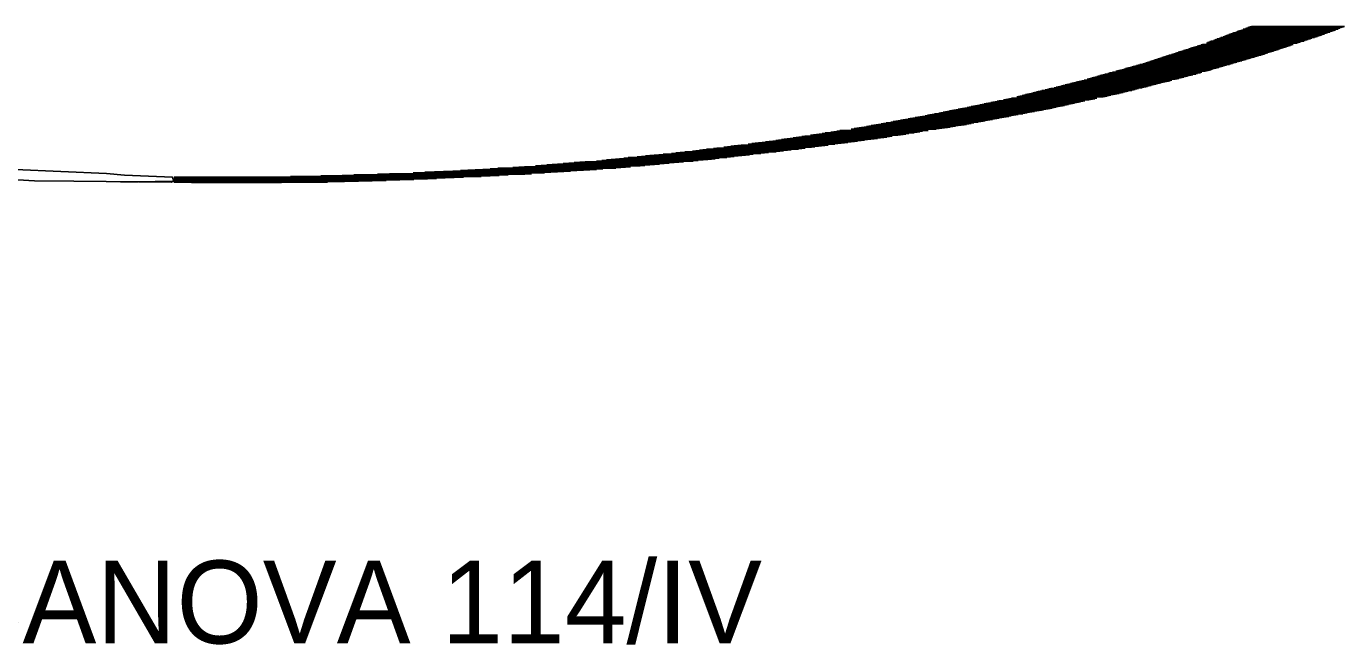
# Model space of a CAD drawing. Extents: x -706631 to -706106, y -1036183 to -1035074.
# Drawn here: x -706129.35 to -706117.43, y -1035971.15 to -1035965.56 of the extents above; entities that cross this region are included whole.
import ezdxf

# ---------------------------------------------------------------- set-up
doc = ezdxf.new("R2010")
doc.units = 0
doc.layers.add('Vrstva 54', color=7, linetype='Continuous')

msp = doc.modelspace()

# ---------------------------------------------------------------- linework, layer by layer
at = {"layer": 'Vrstva 54'}
for p, q in [((-706118.296, -1035965.565), (-706117.453, -1035965.565)), ((-706118.286, -1035965.561), (-706117.442, -1035965.561)), ((-706118.274, -1035965.558), (-706117.431, -1035965.558)), ((-706118.617, -1035965.685), (-706117.787, -1035965.685)), ((-706118.606, -1035965.681), (-706117.774, -1035965.681)), ((-706118.595, -1035965.678), (-706117.762, -1035965.678)), ((-706118.584, -1035965.672), (-706117.749, -1035965.672)), ((-706118.574, -1035965.67), (-706117.738, -1035965.67)), ((-706118.563, -1035965.665), (-706117.726, -1035965.665)), ((-706118.552, -1035965.66), (-706117.713, -1035965.66)), ((-706118.541, -1035965.658), (-706117.702, -1035965.658)), ((-706118.53, -1035965.653), (-706117.689, -1035965.653)), ((-706118.52, -1035965.649), (-706117.677, -1035965.649)), ((-706118.509, -1035965.645), (-706117.665, -1035965.645)), ((-706118.499, -1035965.642), (-706117.653, -1035965.642)), ((-706118.489, -1035965.638), (-706117.641, -1035965.638)), ((-706118.477, -1035965.633), (-706117.63, -1035965.633)), ((-706118.468, -1035965.63), (-706117.62, -1035965.63)), ((-706118.457, -1035965.626), (-706117.609, -1035965.626)), ((-706118.445, -1035965.621), (-706117.597, -1035965.621)), ((-706118.435, -1035965.617), (-706117.587, -1035965.617)), ((-706118.414, -1035965.61), (-706117.566, -1035965.61)), ((-706118.403, -1035965.605), (-706117.558, -1035965.605)), ((-706118.393, -1035965.603), (-706117.547, -1035965.603)), ((-706118.381, -1035965.598), (-706117.536, -1035965.598)), ((-706118.371, -1035965.594), (-706117.526, -1035965.594)), ((-706118.361, -1035965.591), (-706117.514, -1035965.591)), ((-706118.349, -1035965.584), (-706117.504, -1035965.584)), ((-706118.339, -1035965.582), (-706117.493, -1035965.582)), ((-706118.328, -1035965.577), (-706117.483, -1035965.577)), ((-706118.318, -1035965.574), (-706117.474, -1035965.574)), ((-706118.307, -1035965.569), (-706117.463, -1035965.569)), ((-706118.962, -1035965.8), (-706118.137, -1035965.8)), ((-706118.947, -1035965.798), (-706118.125, -1035965.798)), ((-706118.935, -1035965.793), (-706118.112, -1035965.793)), ((-706118.924, -1035965.788), (-706118.1, -1035965.788)), ((-706118.911, -1035965.786), (-706118.088, -1035965.786)), ((-706118.9, -1035965.782), (-706118.075, -1035965.782)), ((-706118.887, -1035965.776), (-706118.064, -1035965.776)), ((-706118.876, -1035965.774), (-706118.052, -1035965.774)), ((-706118.863, -1035965.769), (-706118.04, -1035965.769)), ((-706118.85, -1035965.767), (-706118.029, -1035965.767)), ((-706118.839, -1035965.761), (-706118.015, -1035965.761)), ((-706118.826, -1035965.756), (-706118.003, -1035965.756)), ((-706118.814, -1035965.753), (-706117.991, -1035965.753)), ((-706118.802, -1035965.749), (-706117.98, -1035965.749)), ((-706118.789, -1035965.745), (-706117.968, -1035965.745)), ((-706118.776, -1035965.742), (-706117.956, -1035965.742)), ((-706118.764, -1035965.737), (-706117.944, -1035965.737)), ((-706118.752, -1035965.735), (-706117.931, -1035965.735)), ((-706118.74, -1035965.73), (-706117.919, -1035965.73)), ((-706118.728, -1035965.725), (-706117.908, -1035965.725)), ((-706118.716, -1035965.722), (-706117.895, -1035965.722)), ((-706118.681, -1035965.71), (-706117.859, -1035965.71)), ((-706118.67, -1035965.705), (-706117.847, -1035965.705)), ((-706118.659, -1035965.702), (-706117.834, -1035965.702)), ((-706118.649, -1035965.696), (-706117.823, -1035965.696)), ((-706118.639, -1035965.693), (-706117.81, -1035965.693)), ((-706118.628, -1035965.691), (-706117.799, -1035965.691)), ((-706119.342, -1035965.92), (-706118.543, -1035965.92)), ((-706119.327, -1035965.917), (-706118.528, -1035965.917)), ((-706119.313, -1035965.913), (-706118.514, -1035965.913)), ((-706119.299, -1035965.91), (-706118.5, -1035965.91)), ((-706119.284, -1035965.904), (-706118.487, -1035965.904)), ((-706119.27, -1035965.902), (-706118.473, -1035965.902)), ((-706119.256, -1035965.896), (-706118.46, -1035965.896)), ((-706119.242, -1035965.895), (-706118.445, -1035965.895)), ((-706119.23, -1035965.889), (-706118.432, -1035965.889)), ((-706119.218, -1035965.885), (-706118.418, -1035965.885)), ((-706119.206, -1035965.881), (-706118.405, -1035965.881)), ((-706119.194, -1035965.876), (-706118.391, -1035965.876)), ((-706119.182, -1035965.873), (-706118.378, -1035965.873)), ((-706119.169, -1035965.869), (-706118.362, -1035965.869)), ((-706119.157, -1035965.865), (-706118.348, -1035965.865)), ((-706119.144, -1035965.861), (-706118.335, -1035965.861)), ((-706119.132, -1035965.858), (-706118.321, -1035965.858)), ((-706119.121, -1035965.853), (-706118.308, -1035965.853)), ((-706119.106, -1035965.849), (-706118.294, -1035965.849)), ((-706119.095, -1035965.846), (-706118.281, -1035965.846)), ((-706119.083, -1035965.841), (-706118.266, -1035965.841)), ((-706119.071, -1035965.837), (-706118.253, -1035965.837)), ((-706119.059, -1035965.834), (-706118.24, -1035965.834)), ((-706119.047, -1035965.828), (-706118.226, -1035965.828)), ((-706119.034, -1035965.826), (-706118.211, -1035965.826)), ((-706119.021, -1035965.82), (-706118.198, -1035965.82)), ((-706119.01, -1035965.819), (-706118.185, -1035965.819)), ((-706118.998, -1035965.813), (-706118.172, -1035965.813)), ((-706118.985, -1035965.809), (-706118.16, -1035965.809)), ((-706118.973, -1035965.806), (-706118.149, -1035965.806)), ((-706119.759, -1035966.037), (-706118.963, -1035966.037)), ((-706119.745, -1035966.032), (-706118.946, -1035966.032)), ((-706119.731, -1035966.029), (-706118.931, -1035966.029)), ((-706119.717, -1035966.025), (-706118.916, -1035966.025)), ((-706119.702, -1035966.022), (-706118.9, -1035966.022)), ((-706119.688, -1035966.017), (-706118.885, -1035966.017)), ((-706119.673, -1035966.013), (-706118.869, -1035966.013)), ((-706119.659, -1035966.01), (-706118.852, -1035966.01)), ((-706119.644, -1035966.004), (-706118.837, -1035966.004)), ((-706119.63, -1035966), (-706118.82, -1035966)), ((-706119.615, -1035965.997), (-706118.805, -1035965.997)), ((-706119.601, -1035965.992), (-706118.79, -1035965.992)), ((-706119.586, -1035965.99), (-706118.776, -1035965.99)), ((-706119.573, -1035965.985), (-706118.763, -1035965.985)), ((-706119.559, -1035965.98), (-706118.748, -1035965.98)), ((-706119.545, -1035965.978), (-706118.735, -1035965.978)), ((-706119.529, -1035965.973), (-706118.722, -1035965.973)), ((-706119.5, -1035965.964), (-706118.693, -1035965.964)), ((-706119.486, -1035965.96), (-706118.679, -1035965.96)), ((-706119.472, -1035965.957), (-706118.666, -1035965.957)), ((-706119.458, -1035965.953), (-706118.652, -1035965.953)), ((-706119.442, -1035965.95), (-706118.639, -1035965.95)), ((-706119.428, -1035965.946), (-706118.625, -1035965.946)), ((-706119.414, -1035965.94), (-706118.611, -1035965.94)), ((-706119.4, -1035965.936), (-706118.597, -1035965.936)), ((-706119.386, -1035965.934), (-706118.584, -1035965.934)), ((-706119.37, -1035965.929), (-706118.57, -1035965.929)), ((-706119.355, -1035965.925), (-706118.556, -1035965.925)), ((-706120.25, -1035966.16), (-706119.453, -1035966.16)), ((-706120.235, -1035966.156), (-706119.435, -1035966.156)), ((-706120.219, -1035966.152), (-706119.419, -1035966.152)), ((-706120.202, -1035966.149), (-706119.403, -1035966.149)), ((-706120.186, -1035966.145), (-706119.388, -1035966.145)), ((-706120.17, -1035966.14), (-706119.372, -1035966.14)), ((-706120.154, -1035966.137), (-706119.355, -1035966.137)), ((-706120.138, -1035966.133), (-706119.34, -1035966.133)), ((-706120.122, -1035966.128), (-706119.324, -1035966.128)), ((-706120.105, -1035966.124), (-706119.309, -1035966.124)), ((-706120.088, -1035966.121), (-706119.294, -1035966.121)), ((-706120.057, -1035966.113), (-706119.262, -1035966.113)), ((-706120.039, -1035966.108), (-706119.247, -1035966.108)), ((-706120.023, -1035966.104), (-706119.23, -1035966.104)), ((-706120.007, -1035966.102), (-706119.215, -1035966.102)), ((-706119.992, -1035966.097), (-706119.198, -1035966.097)), ((-706119.977, -1035966.093), (-706119.182, -1035966.093)), ((-706119.959, -1035966.087), (-706119.168, -1035966.087)), ((-706119.943, -1035966.085), (-706119.152, -1035966.085)), ((-706119.926, -1035966.08), (-706119.136, -1035966.08)), ((-706119.91, -1035966.076), (-706119.121, -1035966.076)), ((-706119.895, -1035966.073), (-706119.104, -1035966.073)), ((-706119.879, -1035966.068), (-706119.089, -1035966.068)), ((-706119.862, -1035966.064), (-706119.073, -1035966.064)), ((-706119.846, -1035966.061), (-706119.058, -1035966.061)), ((-706119.832, -1035966.057), (-706119.042, -1035966.057)), ((-706119.817, -1035966.053), (-706119.025, -1035966.053)), ((-706119.804, -1035966.05), (-706119.01, -1035966.05)), ((-706119.788, -1035966.045), (-706118.994, -1035966.045)), ((-706120.789, -1035966.28), (-706120.003, -1035966.28)), ((-706120.769, -1035966.276), (-706119.984, -1035966.276)), ((-706120.75, -1035966.273), (-706119.966, -1035966.273)), ((-706120.73, -1035966.268), (-706119.947, -1035966.268)), ((-706120.71, -1035966.266), (-706119.929, -1035966.266)), ((-706120.691, -1035966.26), (-706119.91, -1035966.26)), ((-706120.672, -1035966.255), (-706119.893, -1035966.255)), ((-706120.652, -1035966.252), (-706119.874, -1035966.252)), ((-706120.632, -1035966.247), (-706119.855, -1035966.247)), ((-706120.613, -1035966.245), (-706119.837, -1035966.245)), ((-706120.593, -1035966.24), (-706119.819, -1035966.24)), ((-706120.574, -1035966.236), (-706119.8, -1035966.236)), ((-706120.554, -1035966.233), (-706119.782, -1035966.233)), ((-706120.515, -1035966.223), (-706119.745, -1035966.223)), ((-706120.496, -1035966.221), (-706119.728, -1035966.221)), ((-706120.478, -1035966.217), (-706119.71, -1035966.217)), ((-706120.462, -1035966.215), (-706119.69, -1035966.215)), ((-706120.445, -1035966.208), (-706119.672, -1035966.208)), ((-706120.396, -1035966.196), (-706119.616, -1035966.196)), ((-706120.38, -1035966.193), (-706119.598, -1035966.193)), ((-706120.365, -1035966.189), (-706119.58, -1035966.189)), ((-706120.348, -1035966.184), (-706119.562, -1035966.184)), ((-706120.332, -1035966.182), (-706119.545, -1035966.182)), ((-706120.316, -1035966.176), (-706119.525, -1035966.176)), ((-706120.299, -1035966.172), (-706119.507, -1035966.172)), ((-706120.282, -1035966.168), (-706119.49, -1035966.168)), ((-706120.267, -1035966.165), (-706119.471, -1035966.165)), ((-706121.403, -1035966.4), (-706120.617, -1035966.4)), ((-706121.38, -1035966.395), (-706120.597, -1035966.395)), ((-706121.359, -1035966.393), (-706120.576, -1035966.393)), ((-706121.337, -1035966.388), (-706120.554, -1035966.388)), ((-706121.316, -1035966.383), (-706120.532, -1035966.383)), ((-706121.292, -1035966.38), (-706120.512, -1035966.38)), ((-706121.27, -1035966.376), (-706120.491, -1035966.376)), ((-706121.249, -1035966.373), (-706120.469, -1035966.373)), ((-706121.226, -1035966.369), (-706120.447, -1035966.369)), ((-706121.204, -1035966.363), (-706120.426, -1035966.363)), ((-706121.182, -1035966.36), (-706120.405, -1035966.36)), ((-706121.16, -1035966.356), (-706120.385, -1035966.356)), ((-706121.141, -1035966.351), (-706120.364, -1035966.351)), ((-706121.121, -1035966.349), (-706120.342, -1035966.349)), ((-706121.101, -1035966.344), (-706120.322, -1035966.344)), ((-706121.082, -1035966.341), (-706120.301, -1035966.341)), ((-706121.063, -1035966.336), (-706120.28, -1035966.336)), ((-706121.042, -1035966.332), (-706120.259, -1035966.332)), ((-706121.024, -1035966.329), (-706120.237, -1035966.329)), ((-706121.004, -1035966.323), (-706120.216, -1035966.323)), ((-706120.985, -1035966.319), (-706120.194, -1035966.319)), ((-706120.965, -1035966.316), (-706120.173, -1035966.316)), ((-706120.945, -1035966.312), (-706120.153, -1035966.312)), ((-706120.926, -1035966.308), (-706120.132, -1035966.308)), ((-706120.906, -1035966.305), (-706120.112, -1035966.305)), ((-706120.888, -1035966.3), (-706120.094, -1035966.3)), ((-706120.866, -1035966.297), (-706120.077, -1035966.297)), ((-706120.846, -1035966.291), (-706120.058, -1035966.291)), ((-706120.827, -1035966.288), (-706120.039, -1035966.288)), ((-706120.809, -1035966.284), (-706120.021, -1035966.284)), ((-706122.079, -1035966.515), (-706121.298, -1035966.515)), ((-706122.051, -1035966.512), (-706121.274, -1035966.512)), ((-706122.025, -1035966.508), (-706121.249, -1035966.508)), ((-706121.998, -1035966.502), (-706121.224, -1035966.502)), ((-706121.972, -1035966.501), (-706121.199, -1035966.501)), ((-706121.893, -1035966.488), (-706121.124, -1035966.488)), ((-706121.867, -1035966.483), (-706121.099, -1035966.483)), ((-706121.844, -1035966.48), (-706121.075, -1035966.48)), ((-706121.822, -1035966.476), (-706121.049, -1035966.476)), ((-706121.8, -1035966.472), (-706121.024, -1035966.472)), ((-706121.778, -1035966.469), (-706120.999, -1035966.469)), ((-706121.756, -1035966.464), (-706120.974, -1035966.464)), ((-706121.734, -1035966.46), (-706120.949, -1035966.46)), ((-706121.712, -1035966.456), (-706120.925, -1035966.456)), ((-706121.69, -1035966.451), (-706120.9, -1035966.451)), ((-706121.668, -1035966.448), (-706120.873, -1035966.448)), ((-706121.646, -1035966.445), (-706120.85, -1035966.445)), ((-706121.623, -1035966.44), (-706120.829, -1035966.44)), ((-706121.602, -1035966.438), (-706120.808, -1035966.438)), ((-706121.579, -1035966.432), (-706120.785, -1035966.432)), ((-706121.535, -1035966.425), (-706120.744, -1035966.425)), ((-706121.514, -1035966.419), (-706120.722, -1035966.419)), ((-706121.491, -1035966.416), (-706120.701, -1035966.416)), ((-706121.469, -1035966.412), (-706120.681, -1035966.412)), ((-706121.447, -1035966.408), (-706120.66, -1035966.408)), ((-706121.425, -1035966.405), (-706120.639, -1035966.405)), ((-706122.92, -1035966.636), (-706122.132, -1035966.636)), ((-706122.888, -1035966.632), (-706122.102, -1035966.632)), ((-706122.825, -1035966.625), (-706122.043, -1035966.625)), ((-706122.794, -1035966.619), (-706122.014, -1035966.619)), ((-706122.762, -1035966.616), (-706121.984, -1035966.616)), ((-706122.731, -1035966.612), (-706121.954, -1035966.612)), ((-706122.699, -1035966.608), (-706121.925, -1035966.608)), ((-706122.669, -1035966.604), (-706121.895, -1035966.604)), ((-706122.636, -1035966.599), (-706121.865, -1035966.599)), ((-706122.604, -1035966.597), (-706121.836, -1035966.597)), ((-706122.577, -1035966.591), (-706121.805, -1035966.591)), ((-706122.551, -1035966.588), (-706121.775, -1035966.588)), ((-706122.525, -1035966.583), (-706121.746, -1035966.583)), ((-706122.499, -1035966.58), (-706121.716, -1035966.58)), ((-706122.473, -1035966.575), (-706121.687, -1035966.575)), ((-706122.445, -1035966.573), (-706121.657, -1035966.573)), ((-706122.419, -1035966.567), (-706121.628, -1035966.567)), ((-706122.393, -1035966.565), (-706121.599, -1035966.565)), ((-706122.367, -1035966.56), (-706121.573, -1035966.56)), ((-706122.341, -1035966.556), (-706121.548, -1035966.556)), ((-706122.314, -1035966.552), (-706121.523, -1035966.552)), ((-706122.262, -1035966.543), (-706121.472, -1035966.543)), ((-706122.236, -1035966.541), (-706121.448, -1035966.541)), ((-706122.208, -1035966.536), (-706121.423, -1035966.536)), ((-706122.183, -1035966.533), (-706121.399, -1035966.533)), ((-706122.157, -1035966.528), (-706121.373, -1035966.528)), ((-706122.13, -1035966.523), (-706121.349, -1035966.523)), ((-706122.104, -1035966.521), (-706121.325, -1035966.521)), ((-706123.99, -1035966.756), (-706123.123, -1035966.756)), ((-706123.949, -1035966.752), (-706123.088, -1035966.752)), ((-706123.91, -1035966.746), (-706123.054, -1035966.746)), ((-706123.871, -1035966.745), (-706123.02, -1035966.745)), ((-706123.831, -1035966.74), (-706122.985, -1035966.74)), ((-706123.792, -1035966.735), (-706122.951, -1035966.735)), ((-706123.754, -1035966.731), (-706122.917, -1035966.731)), ((-706123.715, -1035966.727), (-706122.882, -1035966.727)), ((-706123.675, -1035966.725), (-706122.849, -1035966.725)), ((-706123.635, -1035966.72), (-706122.813, -1035966.72)), ((-706123.596, -1035966.716), (-706122.78, -1035966.716)), ((-706123.519, -1035966.708), (-706122.711, -1035966.708)), ((-706123.48, -1035966.703), (-706122.677, -1035966.703)), ((-706123.441, -1035966.701), (-706122.642, -1035966.701)), ((-706123.4, -1035966.695), (-706122.609, -1035966.695)), ((-706123.361, -1035966.693), (-706122.574, -1035966.693)), ((-706123.33, -1035966.687), (-706122.539, -1035966.687)), ((-706123.298, -1035966.684), (-706122.506, -1035966.684)), ((-706123.266, -1035966.678), (-706122.471, -1035966.678)), ((-706123.235, -1035966.675), (-706122.438, -1035966.675)), ((-706123.203, -1035966.67), (-706122.403, -1035966.67)), ((-706123.172, -1035966.669), (-706122.371, -1035966.669)), ((-706123.14, -1035966.664), (-706122.341, -1035966.664)), ((-706123.108, -1035966.66), (-706122.311, -1035966.66)), ((-706123.046, -1035966.651), (-706122.252, -1035966.651)), ((-706123.014, -1035966.648), (-706122.222, -1035966.648)), ((-706122.982, -1035966.643), (-706122.191, -1035966.643)), ((-706122.951, -1035966.64), (-706122.163, -1035966.64)), ((-706125.663, -1035966.875), (-706124.551, -1035966.875)), ((-706125.581, -1035966.871), (-706124.492, -1035966.871)), ((-706125.497, -1035966.868), (-706124.434, -1035966.868)), ((-706125.429, -1035966.863), (-706124.375, -1035966.863)), ((-706125.361, -1035966.859), (-706124.316, -1035966.859)), ((-706125.294, -1035966.856), (-706124.258, -1035966.856)), ((-706125.225, -1035966.852), (-706124.199, -1035966.852)), ((-706125.158, -1035966.847), (-706124.139, -1035966.847)), ((-706125.09, -1035966.842), (-706124.081, -1035966.842)), ((-706125.024, -1035966.84), (-706124.022, -1035966.84)), ((-706124.955, -1035966.835), (-706123.978, -1035966.835)), ((-706124.899, -1035966.831), (-706123.935, -1035966.831)), ((-706124.849, -1035966.828), (-706123.89, -1035966.828)), ((-706124.748, -1035966.82), (-706123.803, -1035966.82)), ((-706124.699, -1035966.816), (-706123.76, -1035966.816)), ((-706124.648, -1035966.812), (-706123.716, -1035966.812)), ((-706124.599, -1035966.807), (-706123.672, -1035966.807)), ((-706124.549, -1035966.804), (-706123.628, -1035966.804)), ((-706124.498, -1035966.798), (-706123.585, -1035966.798)), ((-706124.449, -1035966.796), (-706123.54, -1035966.796)), ((-706124.399, -1035966.791), (-706123.496, -1035966.791)), ((-706124.349, -1035966.788), (-706123.453, -1035966.788)), ((-706124.299, -1035966.784), (-706123.41, -1035966.784)), ((-706124.199, -1035966.777), (-706123.322, -1035966.777)), ((-706124.148, -1035966.771), (-706123.278, -1035966.771)), ((-706124.106, -1035966.767), (-706123.234, -1035966.767)), ((-706124.066, -1035966.763), (-706123.192, -1035966.763)), ((-706124.027, -1035966.759), (-706123.157, -1035966.759)), ((-706128.5, -1035966.968), (-706128.032, -1035966.96)), ((-706128.02, -1035966.96), (-706126.351, -1035966.96)), ((-706128.02, -1035966.963), (-706126.477, -1035966.963)), ((-706128.02, -1035966.968), (-706126.631, -1035966.968)), ((-706128.018, -1035966.923), (-706125.401, -1035966.923)), ((-706128.018, -1035966.927), (-706125.484, -1035966.927)), ((-706128.018, -1035966.93), (-706125.565, -1035966.93)), ((-706128.018, -1035966.936), (-706125.645, -1035966.936)), ((-706128.018, -1035966.938), (-706125.725, -1035966.938)), ((-706128.018, -1035966.945), (-706125.85, -1035966.945)), ((-706128.018, -1035966.947), (-706125.976, -1035966.947)), ((-706128.018, -1035966.952), (-706126.1, -1035966.952)), ((-706128.018, -1035966.956), (-706126.226, -1035966.956)), ((-706127.861, -1035966.971), (-706127.047, -1035966.971)), ((-706126.965, -1035966.916), (-706125.24, -1035966.916)), ((-706126.69, -1035966.912), (-706125.158, -1035966.912)), ((-706126.499, -1035966.907), (-706125.078, -1035966.907)), ((-706126.392, -1035966.903), (-706124.997, -1035966.903)), ((-706126.177, -1035966.895), (-706124.845, -1035966.895)), ((-706126.07, -1035966.892), (-706124.785, -1035966.892)), ((-706125.856, -1035966.884), (-706124.668, -1035966.884)), ((-706125.749, -1035966.879), (-706124.61, -1035966.879))]:
    msp.add_line(p, q, dxfattribs=at)
msp.add_lwpolyline([(-706130.335, -1035966.892), (-706129.28, -1035966.957), (-706128.926, -1035966.96), (-706128.044, -1035966.968), (-706128.021, -1035966.957), (-706128.032, -1035966.923), (-706128.468, -1035966.905), (-706128.631, -1035966.891), (-706129.456, -1035966.852)], dxfattribs=at)

# ---------------------------------------------------------------- texts
msp.add_text(' ROKYCANOVA 114/IV', height=0.75, rotation=0, dxfattribs=at).set_placement((-706133.235, -1035971.143))

doc.saveas('drawing.dxf')
